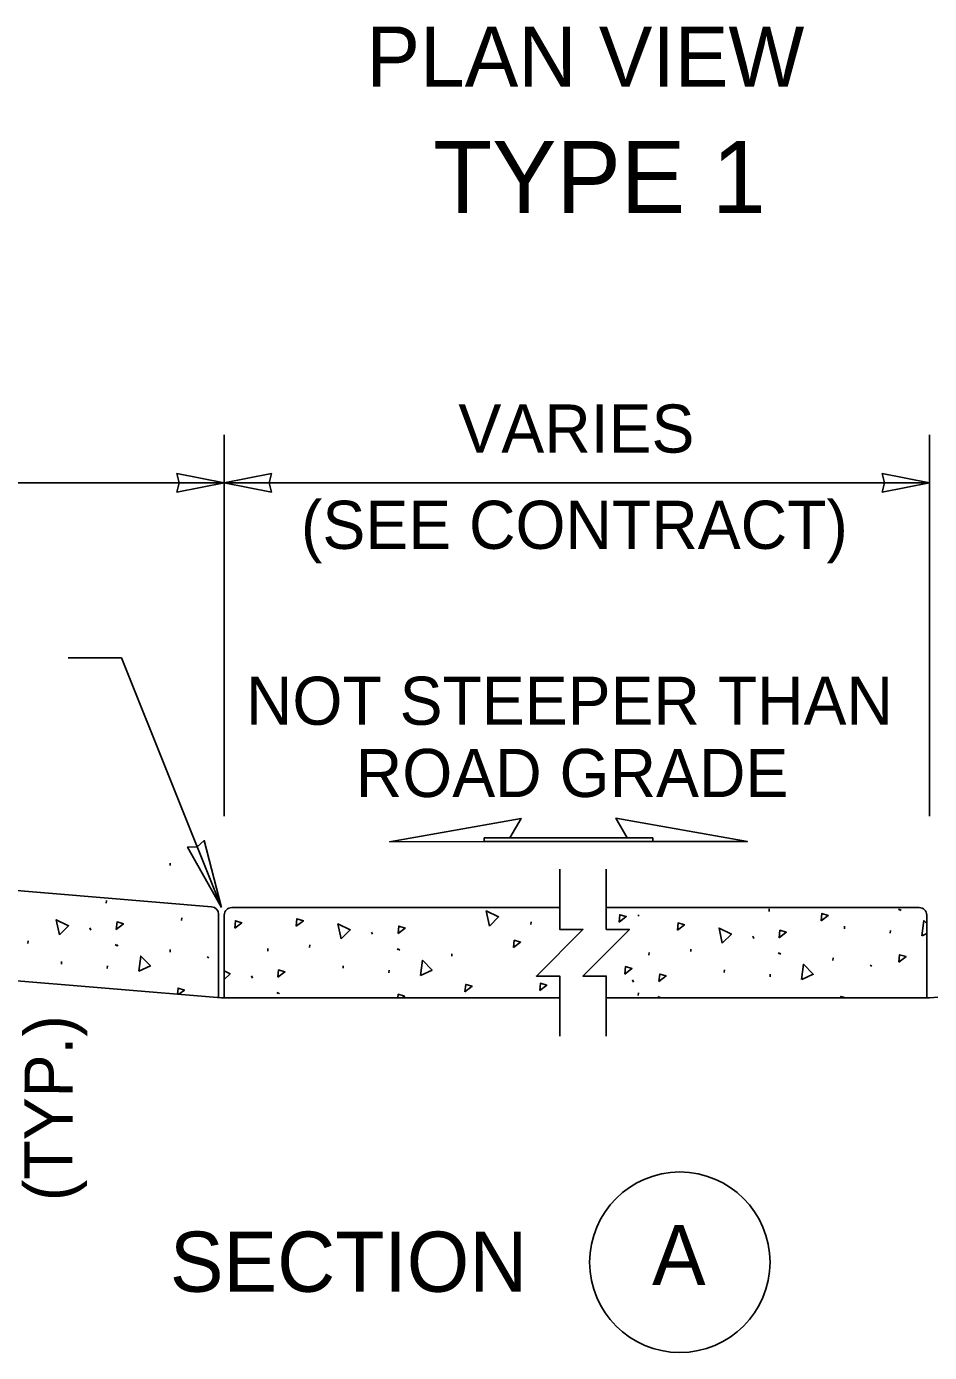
# Model space of a CAD drawing. Extents: x 99862 to 103151, y 100000 to 105076.
# Drawn here: x 100316.6 to 100616.9, y 100983.8 to 101424.6 of the extents above; entities that cross this region are included whole.
import ezdxf

# ---------------------------------------------------------------- set-up
doc = ezdxf.new("R2010")
doc.units = 0
for name, color, linetype in [('Level 13', 7, 'Continuous'), ('Level 15', 7, 'Continuous'), ('Level 20', 7, 'Continuous'), ('Level 26', 7, 'Continuous'), ('Level 9', 7, 'Continuous')]:
    doc.layers.add(name, color=color, linetype=linetype)

msp = doc.modelspace()

# ---------------------------------------------------------------- linework, layer by layer
at = {"layer": 'Level 13'}
for p, q in [((100364.31, 101146.49), (100364.37, 101145.62)), ((100343.08, 101133.13), (100343.14, 101134)), ((100343.08, 101133.13), (100343.14, 101134)), ((100520.11, 101128.86), (100520.14, 101129.29)), ((100520.11, 101128.86), (100520.14, 101129.29)), ((100563.52, 101130.37), (100563.58, 101131.25)), ((100563.52, 101130.37), (100563.58, 101131.25)), ((100577.45, 101131.57), (100577.45, 101131.67)), ((100577.45, 101131.57), (100577.45, 101131.67)), ((100606.51, 101131.18), (100607.02, 101130.8)), ((100606.51, 101131.18), (100607.02, 101130.8)), ((100606.91, 101131.11), (100607.43, 101130.73)), ((100606.91, 101131.11), (100607.43, 101130.73)), ((100337.64, 101124.9), (100337.99, 101124.18)), ((100337.64, 101124.9), (100337.99, 101124.18)), ((100368.12, 101127.41), (100368.18, 101128.28)), ((100368.12, 101127.41), (100368.18, 101128.28)), ((100484.31, 101126.03), (100484.37, 101126.9)), ((100484.31, 101126.03), (100484.37, 101126.9)), ((100588.56, 101124.65), (100588.63, 101125.52)), ((100588.56, 101124.65), (100588.63, 101125.52)), ((100317.03, 101119.78), (100317.09, 101120.65)), ((100317.03, 101119.78), (100317.09, 101120.65)), ((100431.32, 101123.52), (100431.68, 101122.8)), ((100431.32, 101123.52), (100431.68, 101122.8)), ((100558.08, 101122.14), (100558.43, 101121.42)), ((100558.08, 101122.14), (100558.43, 101121.42)), ((100603.83, 101123.2), (100603.89, 101124.08)), ((100603.83, 101123.2), (100603.89, 101124.08)), ((100346.09, 101119.39), (100346.61, 101119.01)), ((100346.09, 101119.39), (100346.61, 101119.01)), ((100346.5, 101119.32), (100347.01, 101118.94)), ((100346.5, 101119.32), (100347.01, 101118.94)), ((100364.31, 101116.84), (100364.37, 101117.72)), ((100396.79, 101117.2), (100396.85, 101118.07)), ((100396.79, 101117.2), (100396.85, 101118.07)), ((100410.72, 101118.4), (100410.78, 101119.27)), ((100410.72, 101118.4), (100410.78, 101119.27)), ((100439.78, 101118.01), (100440.3, 101117.63)), ((100439.78, 101118.01), (100440.3, 101117.63)), ((100440.18, 101117.94), (100440.7, 101117.56)), ((100440.18, 101117.94), (100440.7, 101117.56)), ((100458, 101115.47), (100458.06, 101116.34)), ((100458, 101115.47), (100458.06, 101116.34)), ((100523.55, 101115.82), (100523.61, 101116.7)), ((100523.55, 101115.82), (100523.61, 101116.7)), ((100537.48, 101117.02), (100537.54, 101117.89)), ((100537.48, 101117.02), (100537.54, 101117.89)), ((100566.53, 101116.63), (100567.05, 101116.25)), ((100566.53, 101116.63), (100567.05, 101116.25)), ((100566.94, 101116.56), (100567.45, 101116.19)), ((100566.94, 101116.56), (100567.45, 101116.19)), ((100328.15, 101112.86), (100328.21, 101113.73)), ((100328.15, 101112.86), (100328.21, 101113.73)), ((100343.42, 101111.41), (100343.48, 101112.28)), ((100343.42, 101111.41), (100343.48, 101112.28)), ((100376.69, 101115.3), (100377.2, 101114.92)), ((100376.69, 101115.3), (100377.2, 101114.92)), ((100421.84, 101111.48), (100421.9, 101112.35)), ((100421.84, 101111.48), (100421.9, 101112.35)), ((100584.76, 101114.09), (100584.82, 101114.96)), ((100584.76, 101114.09), (100584.82, 101114.96)), ((100597.13, 101112.54), (100597.65, 101112.16)), ((100597.13, 101112.54), (100597.65, 101112.16)), ((100391.35, 101108.97), (100391.71, 101108.25)), ((100391.35, 101108.97), (100391.71, 101108.25)), ((100437.11, 101110.03), (100437.17, 101110.91)), ((100437.11, 101110.03), (100437.17, 101110.91)), ((100518.11, 101107.6), (100518.46, 101106.88)), ((100518.11, 101107.6), (100518.46, 101106.88)), ((100548.59, 101110.1), (100548.65, 101110.98)), ((100548.59, 101110.1), (100548.65, 101110.98)), ((100563.86, 101108.66), (100563.92, 101109.53)), ((100563.86, 101108.66), (100563.92, 101109.53)), ((100399.81, 101103.46), (100400.32, 101103.08)), ((100399.81, 101103.46), (100400.32, 101103.08)), ((100400.21, 101103.39), (100400.73, 101103.02)), ((100400.21, 101103.39), (100400.73, 101103.02)), ((100520, 101102.47), (100520.06, 101103.34)), ((100520, 101102.47), (100520.06, 101103.34)), ((100418.08, 101101.67), (100418.09, 101101.79)), ((100418.08, 101101.67), (100418.09, 101101.79)), ((100526.56, 101102.09), (100527.08, 101101.71)), ((100526.56, 101102.09), (100527.08, 101101.71)), ((100526.96, 101102.02), (100527.44, 101101.67)), ((100526.96, 101102.02), (100527.44, 101101.67))]:
    msp.add_line(p, q, dxfattribs=at)
for points in [[(100493.87, 101144.41), (100493.87, 101124.41), (100501.61, 101124.41), (100486.12, 101108.92), (100493.87, 101108.92), (100493.87, 101088.92)], [(100493.87, 101144.41), (100493.87, 101124.41), (100501.61, 101124.41), (100486.12, 101108.92), (100493.87, 101108.92), (100493.87, 101088.92)], [(100509.35, 101144.41), (100509.35, 101124.41), (100517.09, 101124.41), (100501.61, 101108.92), (100509.35, 101108.92), (100509.35, 101088.92)], [(100509.35, 101144.41), (100509.35, 101124.41), (100517.09, 101124.41), (100501.61, 101108.92), (100509.35, 101108.92), (100509.35, 101088.92)], [(100470.55, 101125.55), (100469.47, 101130.56), (100473.58, 101128.56), (100470.61, 101125.6)], [(100470.55, 101125.55), (100469.47, 101130.56), (100473.58, 101128.56), (100470.61, 101125.6)], [(100513.63, 101126.85), (100513.87, 101129.3), (100515.99, 101128.66), (100513.63, 101126.85)], [(100513.63, 101126.85), (100513.87, 101129.3), (100515.99, 101128.66), (100513.63, 101126.85)], [(100580.85, 101127.28), (100581.09, 101129.73), (100583.21, 101129.09), (100580.85, 101127.28)], [(100580.85, 101127.28), (100581.09, 101129.73), (100583.21, 101129.09), (100580.85, 101127.28)], [(100327.5, 101122.61), (100326.43, 101127.62), (100330.54, 101125.62), (100327.57, 101122.66)], [(100327.5, 101122.61), (100326.43, 101127.62), (100330.54, 101125.62), (100327.57, 101122.66)], [(100346.43, 101124.43), (100346.68, 101126.88), (100348.8, 101126.23), (100346.43, 101124.43)], [(100346.43, 101124.43), (100346.68, 101126.88), (100348.8, 101126.23), (100346.43, 101124.43)], [(100385.8, 101124.82), (100386.04, 101127.27), (100388.16, 101126.63), (100385.8, 101124.82)], [(100385.8, 101124.82), (100386.04, 101127.27), (100388.16, 101126.63), (100385.8, 101124.82)], [(100406.26, 101125.52), (100406.5, 101127.97), (100408.63, 101127.32), (100406.26, 101125.52)], [(100406.26, 101125.52), (100406.5, 101127.97), (100408.63, 101127.32), (100406.26, 101125.52)], [(100421.19, 101121.23), (100420.11, 101126.24), (100424.23, 101124.24), (100421.26, 101121.29)], [(100421.19, 101121.23), (100420.11, 101126.24), (100424.23, 101124.24), (100421.26, 101121.29)], [(100440.12, 101123.05), (100440.36, 101125.5), (100442.49, 101124.86), (100440.12, 101123.05)], [(100440.12, 101123.05), (100440.36, 101125.5), (100442.49, 101124.86), (100440.12, 101123.05)], [(100533.01, 101124.14), (100533.26, 101126.59), (100535.38, 101125.94), (100533.01, 101124.14)], [(100533.01, 101124.14), (100533.26, 101126.59), (100535.38, 101125.94), (100533.01, 101124.14)], [(100547.94, 101119.85), (100546.87, 101124.86), (100550.98, 101122.86), (100548.01, 101119.91)], [(100547.94, 101119.85), (100546.87, 101124.86), (100550.98, 101122.86), (100548.01, 101119.91)], [(100614.28, 101122.28), (100614.99, 101127.36), (100615.92, 101126.4)], [(100614.28, 101122.28), (100614.99, 101127.36), (100615.92, 101126.4)], [(100478.52, 101118.39), (100478.77, 101120.84), (100480.89, 101120.2), (100478.52, 101118.39)], [(100478.52, 101118.39), (100478.77, 101120.84), (100480.89, 101120.2), (100478.52, 101118.39)], [(100566.87, 101121.67), (100567.12, 101124.12), (100569.24, 101123.48), (100566.87, 101121.67)], [(100566.87, 101121.67), (100567.12, 101124.12), (100569.24, 101123.48), (100566.87, 101121.67)], [(100615.92, 101123.03), (100614.37, 101122.31)], [(100615.92, 101123.03), (100614.37, 101122.31)], [(100606.68, 101113.56), (100606.92, 101116.01), (100609.05, 101115.37), (100606.68, 101113.56)], [(100606.68, 101113.56), (100606.92, 101116.01), (100609.05, 101115.37), (100606.68, 101113.56)], [(100353.87, 101110.49), (100354.57, 101115.57), (100357.75, 101112.28), (100353.95, 101110.52)], [(100353.87, 101110.49), (100354.57, 101115.57), (100357.75, 101112.28), (100353.95, 101110.52)], [(100447.56, 101109.11), (100448.26, 101114.19), (100451.44, 101110.9), (100447.64, 101109.14)], [(100447.56, 101109.11), (100448.26, 101114.19), (100451.44, 101110.9), (100447.64, 101109.14)], [(100515.54, 101109.59), (100515.78, 101112.04), (100517.9, 101111.4), (100515.54, 101109.59)], [(100515.54, 101109.59), (100515.78, 101112.04), (100517.9, 101111.4), (100515.54, 101109.59)], [(100574.31, 101107.73), (100575.01, 101112.81), (100578.19, 101109.53), (100574.39, 101107.76)], [(100574.31, 101107.73), (100575.01, 101112.81), (100578.19, 101109.53), (100574.39, 101107.76)], [(100382.31, 101110.64), (100384.25, 101109.69), (100382.31, 101107.75)], [(100382.31, 101110.64), (100384.25, 101109.69), (100382.31, 101107.75)], [(100400.15, 101108.5), (100400.39, 101110.95), (100402.52, 101110.31), (100400.15, 101108.5)], [(100400.15, 101108.5), (100400.39, 101110.95), (100402.52, 101110.31), (100400.15, 101108.5)], [(100526.9, 101107.12), (100527.14, 101109.57), (100529.27, 101108.93), (100526.9, 101107.12)], [(100526.9, 101107.12), (100527.14, 101109.57), (100529.27, 101108.93), (100526.9, 101107.12)], [(100366.77, 101102.88), (100366.97, 101104.91), (100369.1, 101104.27), (100367.23, 101102.85)], [(100366.77, 101102.88), (100366.97, 101104.91), (100369.1, 101104.27), (100367.23, 101102.85)], [(100440.08, 101101.67), (100440.2, 101102.84), (100442.32, 101102.2), (100441.63, 101101.67)], [(100440.08, 101101.67), (100440.2, 101102.84), (100442.32, 101102.2), (100441.63, 101101.67)], [(100462.38, 101103.7), (100462.62, 101106.15), (100464.74, 101105.5), (100462.38, 101103.7)], [(100462.38, 101103.7), (100462.62, 101106.15), (100464.74, 101105.5), (100462.38, 101103.7)], [(100487.23, 101104.06), (100487.47, 101106.51), (100489.6, 101105.87), (100487.23, 101104.06)], [(100487.23, 101104.06), (100487.47, 101106.51), (100489.6, 101105.87), (100487.23, 101104.06)], [(100587.37, 101101.67), (100587.41, 101102.16), (100589.03, 101101.67)], [(100587.37, 101101.67), (100587.41, 101102.16), (100589.03, 101101.67)]]:
    msp.add_lwpolyline(points, dxfattribs=at)
at = {"layer": 'Level 15'}
for p, q in [((100382.31, 101162.06), (100382.31, 101288.87)), ((100382.31, 101162.06), (100382.31, 101288.87)), ((100616.85, 101162.06), (100616.85, 101288.87)), ((100616.85, 101162.06), (100616.85, 101288.87)), ((100022.31, 101272.87), (100382.31, 101272.87)), ((100022.31, 101272.87), (100382.31, 101272.87)), ((100330.47, 101214.75), (100348.13, 101214.75)), ((100381.37, 101131.67), (100348.13, 101214.75))]:
    msp.add_line(p, q, dxfattribs=at)
for points in [[(100382.31, 101272.87), (100366.58, 101269.79), (100367.31, 101272.87), (100366.58, 101275.95)], [(100382.31, 101272.87), (100366.58, 101269.79), (100367.31, 101272.87), (100366.58, 101275.95)], [(100382.31, 101272.87), (100398.03, 101269.79), (100397.3, 101272.87), (100398.03, 101275.95)], [(100382.31, 101272.87), (100398.03, 101269.79), (100397.3, 101272.87), (100398.03, 101275.95)], [(100616.85, 101272.87), (100601.13, 101275.95), (100601.86, 101272.87), (100601.13, 101269.79)], [(100616.85, 101272.87), (100601.13, 101275.95), (100601.86, 101272.87), (100601.13, 101269.79)], [(100381.37, 101131.67), (100375.66, 101153.97), (100373.28, 101151.88), (100370.12, 101151.76)]]:
    msp.add_lwpolyline(points, close=True, dxfattribs=at)
msp.add_lwpolyline([(100616.85, 101272.87), (100382.31, 101272.87)], dxfattribs=at)
msp.add_lwpolyline([(100616.85, 101272.87), (100382.31, 101272.87)], dxfattribs=at)
at = {"layer": 'Level 20'}
for points in [[(100524.81, 101154.9), (100477.32, 101154.86), (100481.05, 101161.34), (100437.31, 101153.58), (100524.81, 101153.66)], [(100524.81, 101154.9), (100477.32, 101154.86), (100481.05, 101161.34), (100437.31, 101153.58), (100524.81, 101153.66)], [(100468.81, 101154.85), (100516.3, 101154.89), (100512.55, 101161.37), (100556.31, 101153.69), (100468.81, 101153.61)], [(100468.81, 101154.85), (100516.3, 101154.89), (100512.55, 101161.37), (100556.31, 101153.69), (100468.81, 101153.61)]]:
    msp.add_lwpolyline(points, close=True, dxfattribs=at)
at = {"layer": 'Level 26'}
for p, q in [((100025.01, 101161.36), (100378.14, 101131.94)), ((100025.01, 101161.36), (100378.14, 101131.94)), ((100381.37, 101101.67), (100022.31, 101131.59)), ((100381.37, 101101.67), (100022.31, 101131.59)), ((100380.43, 101129.45), (100380.43, 101101.67)), ((100380.43, 101129.45), (100380.43, 101101.67)), ((100382.31, 101129.17), (100382.31, 101101.67)), ((100382.31, 101129.17), (100382.31, 101101.67)), ((100384.81, 101131.67), (100493.87, 101131.67)), ((100384.81, 101131.67), (100493.87, 101131.67)), ((100613.42, 101131.67), (100509.35, 101131.67)), ((100613.42, 101131.67), (100509.35, 101131.67)), ((100615.92, 101129.17), (100615.92, 101101.67)), ((100615.92, 101129.17), (100615.92, 101101.67)), ((100616.85, 101101.67), (100975.92, 101131.59)), ((100493.87, 101101.67), (100381.37, 101101.67)), ((100493.87, 101101.67), (100381.37, 101101.67)), ((100509.35, 101101.67), (100616.85, 101101.67)), ((100509.35, 101101.67), (100616.85, 101101.67))]:
    msp.add_line(p, q, dxfattribs=at)
for centre, start, end in [((100377.93, 101129.45), 360, 85.2364), ((100377.93, 101129.45), 360, 85.2364), ((100384.81, 101129.17), 90, 180), ((100384.81, 101129.17), 90, 180), ((100613.42, 101129.17), 0, 90), ((100613.42, 101129.17), 0, 90)]:
    msp.add_arc(centre, 2.5, start, end, dxfattribs=at)
at = {"layer": 'Level 9'}
msp.add_circle((100533.83, 101013.77), 30, dxfattribs=at)

# ---------------------------------------------------------------- texts
at = {"layer": 'Level 20'}
for s, height, p in [('PLAN VIEW', 20, (100429.58, 101404.57)), ('TYPE 1', 24, (100451.81, 101362.57)), ('VARIES ', 16, (100460.2, 101282.92)), ('(SEE CONTRACT)', 16, (100407.84, 101250.92)), ('NOT STEEPER THAN', 16, (100389.54, 101192.43)), ('ROAD GRADE', 16, (100426.07, 101168.43)), ('SECTION', 20, (100364.24, 101003.95)), ('A', 20, (100524.59, 101006.15))]:
    msp.add_text(s, height=height, dxfattribs=at).set_placement(p)
msp.add_text('(TYP.)', height=16, rotation=89.8793, dxfattribs=at).set_placement((100331.82, 101034.08))

doc.saveas('drawing.dxf')
